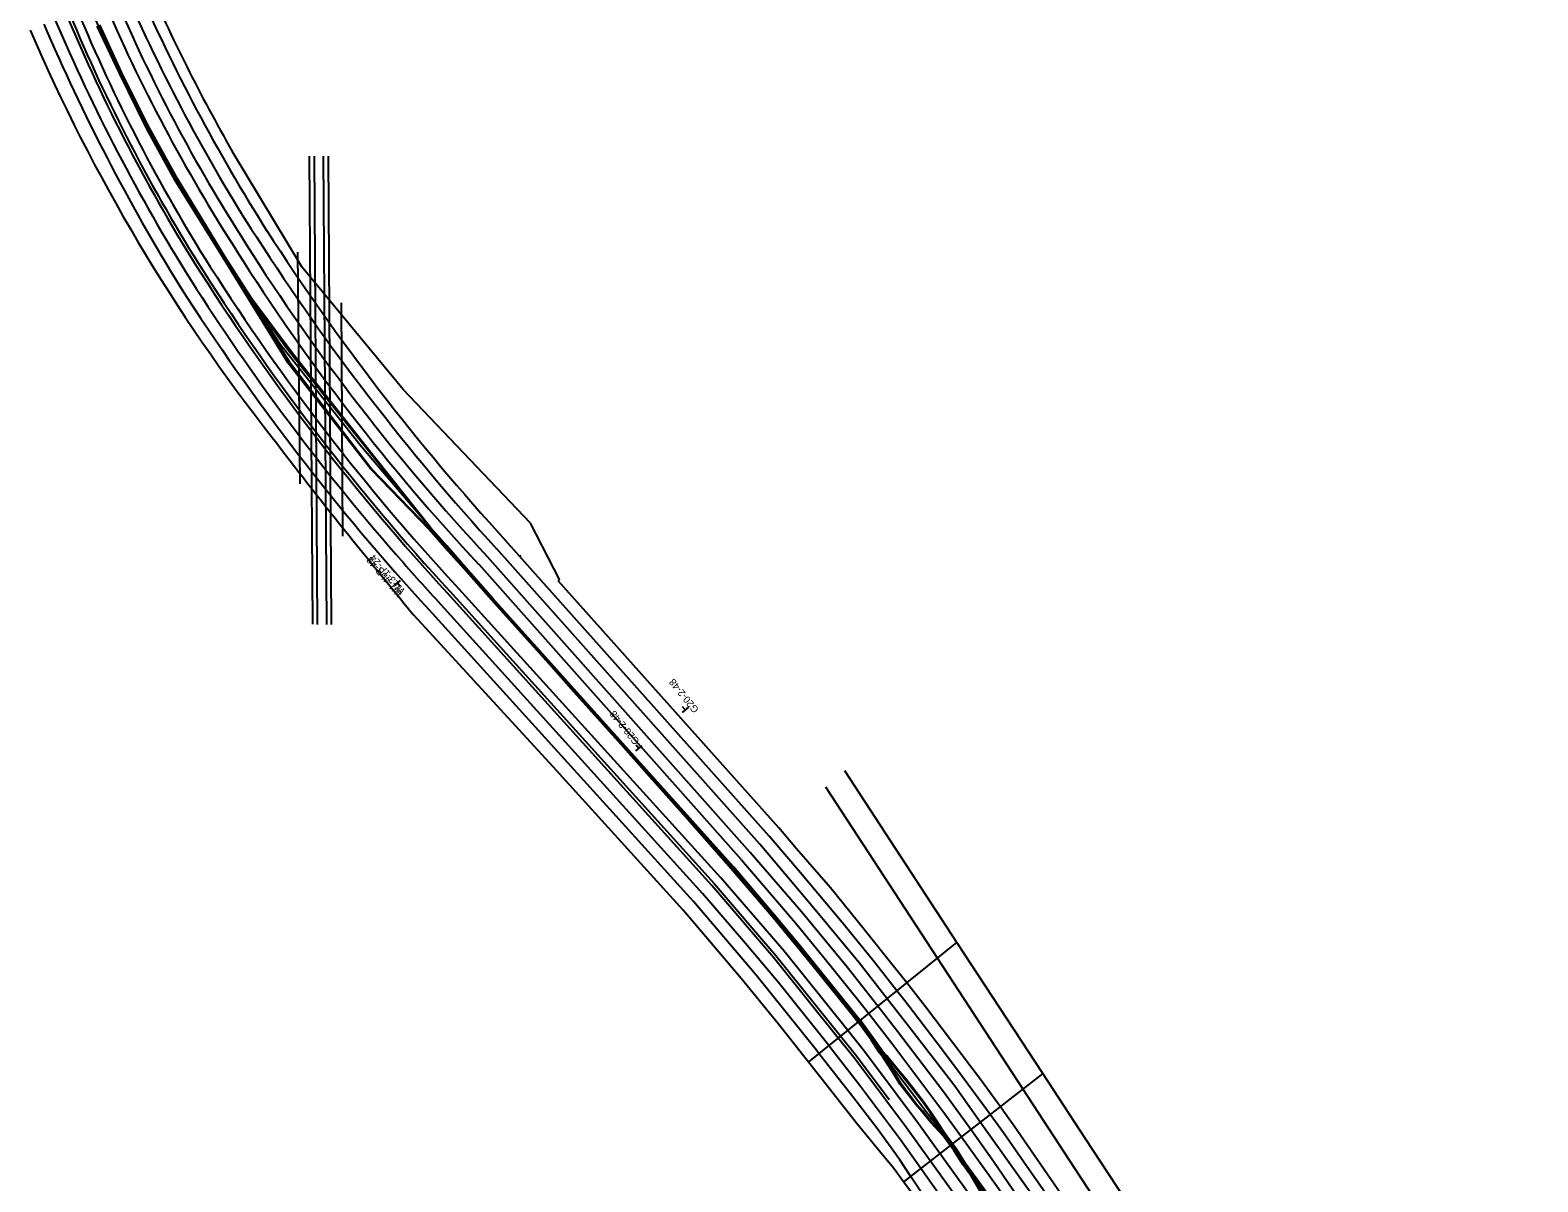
# Model space of a CAD drawing. Extents: x 1691089 to 1704871, y 694247 to 736350.
# Drawn here: x 1695879 to 1697359, y 720467 to 721597 of the extents above; entities that cross this region are included whole.
import ezdxf

# ---------------------------------------------------------------- set-up
doc = ezdxf.new("R2010")
doc.units = 0
for name, color, linetype in [('BR_X_Rail_Text', 7, 'Continuous'), ('BR_X_Slab_Object', 7, 'Continuous'), ('MT_P_Drums', 7, 'Continuous'), ('MT_P_Edge_Line', 7, 'Continuous'), ('PM_P_Channelizing_Line', 7, 'Continuous'), ('PM_X_Channelizing_Line', 7, 'Continuous'), ('PM_X_Dotted_Line', 7, 'Continuous'), ('PM_X_Edge_Line', 7, 'Continuous'), ('PM_X_Lane_Line', 7, 'Continuous'), ('PV_X_EOP', 7, 'Continuous'), ('PV_X_Shoulder', 7, 'Continuous'), ('RD_X_Concrete_Barrier', 7, 'Continuous'), ('SC_Scratch1', 7, 'Continuous'), ('SC_Scratch2', 7, 'Continuous'), ('SN_P_Signs', 7, 'Continuous')]:
    doc.layers.add(name, color=color, linetype=linetype)

msp = doc.modelspace()

# ---------------------------------------------------------------- linework, layer by layer
at = {"layer": 'BR_X_Rail_Text'}
for p, q in [((1696152.9, 721473.9), (1696156.4, 721014.4)), ((1696161.2, 721014.3), (1696158.3, 721473.8)), ((1696166.7, 721473.7), (1696170.1, 721014.2)), ((1696174.9, 721014.2), (1696172.1, 721473.7))]:
    msp.add_line(p, q, dxfattribs=at)
at = {"layer": 'BR_X_Slab_Object'}
for p, q in [((1696141.6, 721379.4), (1696143.8, 721152.3)), ((1696186.2, 721100.8), (1696184.7, 721329.9))]:
    msp.add_line(p, q, dxfattribs=at)
at = {"layer": 'MT_P_Drums'}
msp.add_line((1696901.4, 720309.1), (1696803.1, 720472.6), dxfattribs=at)
msp.add_lwpolyline([(1696291, 721046.9), (1696291, 721046.9), (1696550.5, 720759.9), (1696611.3, 720689.2), (1696690.3, 720590.8), (1696722.5, 720547.9)], dxfattribs=at)
for centre, radius, start, end in [((1697453.6, 722251.7), 1663.1, 202.5428, 212.3875), ((1697945.5, 722571.4), 2249.7, 212.5534, 222.6591)]:
    msp.add_arc(centre, radius, start, end, dxfattribs=at)
at = {"layer": 'MT_P_Edge_Line'}
msp.add_line((1696548.3, 720758), (1696288.8, 721044.9), dxfattribs=at)
for points in [[(1696672.4, 720608.3), (1696609, 720687.3), (1696548.3, 720758)], [(1696720.1, 720546.1), (1696688, 720588.9), (1696672.4, 720608.3)], [(1696762.8, 720487.7), (1696739.4, 720520.3), (1696720.1, 720546.1)], [(1696888.9, 720301.7), (1696809, 720423.3), (1696762.8, 720487.7)]]:
    msp.add_lwpolyline(points, dxfattribs=at)
for centre, radius, start, end in [((1697453.6, 722251.7), 1666.1, 202.5428, 212.3877), ((1697945.5, 722571.4), 2252.7, 212.5533, 222.6591)]:
    msp.add_arc(centre, radius, start, end, dxfattribs=at)
at = {"layer": 'PM_P_Channelizing_Line'}
msp.add_lwpolyline([(1696910.2, 720315.4), (1696907.1, 720320.2), (1696867.4, 720381.7), (1696850.4, 720407.5), (1696800, 720481.6), (1696695.8, 720618.7), (1696638.3, 720693.3), (1696578.4, 720765.8), (1696308.4, 721066.1), (1696204.3, 721188.4), (1696124.9, 721288.6), (1696069.9, 721373.8), (1696004.2, 721483.9), (1695952.8, 721586.7), (1695915.1, 721673.2)], dxfattribs=at)
at = {"layer": 'PM_X_Channelizing_Line'}
for points in [[(1696663.2, 720600.9), (1696613.4, 720663.3), (1696581.4, 720701.2)], [(1696711, 720538.6), (1696693.4, 720562.1), (1696665.9, 720597.4), (1696663.2, 720600.9)], [(1696753.4, 720480.4), (1696733.4, 720508.6), (1696711, 720538.6)], [(1696878.6, 720295.6), (1696837, 720360.8), (1696810.7, 720399.6), (1696753.4, 720480.4)]]:
    msp.add_lwpolyline(points, dxfattribs=at)
at = {"layer": 'PM_X_Dotted_Line'}
for p, q in [((1696539.3, 720750.2), (1696279.8, 721036.7)), ((1696581.4, 720701.2), (1696539.3, 720750.2))]:
    msp.add_line(p, q, dxfattribs=at)
msp.add_arc((1697937, 722563.4), 2253.3, 221.0668, 222.6525, dxfattribs=at)
at = {"layer": 'PM_X_Edge_Line'}
for p, q in [((1696577.5, 720783.1), (1696319.8, 721073)), ((1696557.2, 720765.7), (1696297, 721052.3))]:
    msp.add_line(p, q, dxfattribs=at)
for points in [[(1696577.5, 720783.1), (1696630.4, 720721.5), (1696660, 720685.3), (1696692.5, 720645), (1696702.4, 720632.4)], [(1696681.7, 720615.8), (1696619.3, 720693.5), (1696557.2, 720765.7)], [(1696702.4, 720632.4), (1696724.9, 720603.4), (1696777.1, 720533.9), (1696793.3, 720511.4)], [(1696729.3, 720553.7), (1696698.3, 720595.1), (1696681.7, 720615.8)], [(1696772.3, 720495), (1696749.7, 720526.5), (1696729.3, 720553.7)], [(1696793.3, 720511.4), (1696827.7, 720463.5), (1696874.8, 720395.2), (1696906.7, 720346.8), (1696927.6, 720314.4), (1697062.4, 720097), (1697098.5, 720038.5), (1697133.9, 719981.7), (1697162.2, 719935.7), (1697199.3, 719874.8)], [(1696899.2, 720307.9), (1696819.3, 720429.5), (1696772.3, 720495)]]:
    msp.add_lwpolyline(points, dxfattribs=at)
for centre, radius, start, end in [((1697480.8, 722263.3), 1684.3, 202.5458, 212.2218), ((1697506.5, 722297), 1693.7, 203.2478, 212.7106), ((1697834.5, 722488.4), 2073.2, 212.2654, 223.0597), ((1697936.6, 722564.4), 2230.4, 212.5219, 222.6822)]:
    msp.add_arc(centre, radius, start, end, dxfattribs=at)
at = {"layer": 'PM_X_Lane_Line'}
for p, q in [((1696595.3, 720798.5), (1696336.9, 721088.6)), ((1696586, 720790.5), (1696328.1, 721080.6))]:
    msp.add_line(p, q, dxfattribs=at)
for points in [[(1696711.2, 720639.5), (1696681.3, 720677.8), (1696636.4, 720732.1), (1696586, 720790.5)], [(1696720.4, 720646.9), (1696692.9, 720682), (1696648.3, 720736.2), (1696595.3, 720798.5)], [(1696811.9, 720525.8), (1696786.8, 720561.2), (1696743.7, 720617), (1696720.4, 720646.9)], [(1696802.5, 720518.5), (1696775.9, 720555.5), (1696730.6, 720614.8), (1696711.2, 720639.5)], [(1697081.4, 720110), (1696950.9, 720320.3), (1696884.6, 720422.4), (1696859.8, 720458.5), (1696811.9, 720525.8)], [(1697209.4, 719880.9), (1697169.4, 719945.8), (1696946, 720306.1), (1696902, 720374), (1696825, 720487.3), (1696802.5, 720518.5)]]:
    msp.add_lwpolyline(points, dxfattribs=at)
for centre, radius, start, end in [((1697484.5, 722282.9), 1656.3, 203.1, 212.7129), ((1697502.3, 722296.6), 1666.4, 203.2892, 212.7764), ((1697578.7, 722319.3), 1820, 203.0043, 212.0768), ((1697886.9, 722529.7), 2128.4, 212.4479, 222.9118), ((1698021.9, 722630.4), 2283.9, 212.7617, 222.4608), ((1697937, 722563.4), 2253.3, 212.4985, 221.0668)]:
    msp.add_arc(centre, radius, start, end, dxfattribs=at)
at = {"layer": 'PV_X_EOP'}
for p, q in [((1696604.5, 720806.4), (1696345.9, 721096.7)), ((1696360.8, 721080.4), (1696359.7, 721081.8)), ((1696530.2, 720742.4), (1696270.7, 721028.5)), ((1696873.2, 720573.4), (1696789, 720702.1)), ((1696853.8, 720558.4), (1696769.9, 720686.7))]:
    msp.add_line(p, q, dxfattribs=at)
for points in [[(1696730, 720654.7), (1696706.3, 720684.9), (1696676.3, 720721.7), (1696635.4, 720770.3), (1696604.5, 720806.4)], [(1696653.5, 720593.1), (1696650.8, 720596.6), (1696591.7, 720670), (1696530.2, 720742.4)], [(1696821.5, 720533.3), (1696815.3, 720541.9), (1696794.1, 720570.7), (1696773.9, 720597.7), (1696737.8, 720644.8), (1696730, 720654.7)], [(1696743.5, 720472.7), (1696732.9, 720488.7), (1696710.5, 720519.4), (1696686.8, 720550.6), (1696653.5, 720593.1)], [(1697045.1, 720311.8), (1696915, 720509.5), (1696873.2, 720573.4)], [(1697103.1, 720178.1), (1696904.8, 720480.3), (1696853.8, 720558.4)], [(1697359.2, 719730.4), (1697341, 719753.2), (1697308.3, 719796), (1697294.5, 719815.3), (1697286.5, 719827.3), (1697275.5, 719843.1), (1697259.5, 719867.2), (1697226.8, 719917.4), (1697204.3, 719951.5), (1697169.5, 720005), (1697022.9, 720228.1), (1697002, 720261.3), (1696982.9, 720292.3), (1696952.2, 720341.3), (1696912.9, 720401.2), (1696877.4, 720453.8), (1696857.6, 720482.4), (1696834.7, 720515.2), (1696821.5, 720533.3)], [(1696854.4, 720283), (1696812.4, 720360.8), (1696793.9, 720393.5), (1696768.8, 720434.4), (1696743.5, 720472.7)]]:
    msp.add_lwpolyline(points, dxfattribs=at)
for centre, radius, start, end in [((1697608.4, 722349.5), 1772.3, 203.5031, 212.3583), ((1697687.4, 722372.2), 1952.6, 203.1914, 211.7045), ((1698029.3, 722636.9), 2281.7, 212.7967, 222.4558), ((1698004, 722616.3), 2350.6, 212.7108, 222.4927)]:
    msp.add_arc(centre, radius, start, end, dxfattribs=at)
at = {"layer": 'PV_X_Shoulder'}
for p, q in [((1696077.4, 721478.4), (1696145.5, 721365.4)), ((1696094, 721332.7), (1696068.9, 721373.6)), ((1696096.8, 721333.8), (1696070.6, 721374.7)), ((1696245.2, 721244.8), (1696145.5, 721365.4)), ((1696132.5, 721270.7), (1696094, 721332.7)), ((1696137.3, 721279.6), (1696096.8, 721333.8)), ((1696218.4, 721176.7), (1696137.3, 721279.6)), ((1696213.6, 721166.6), (1696132.5, 721270.7)), ((1696370.2, 721113.6), (1696245.2, 721244.8)), ((1696272.1, 721109.2), (1696218.4, 721176.7)), ((1696213.6, 721166.6), (1696270.8, 721107.4)), ((1696398.8, 721058.3), (1696370.2, 721113.6)), ((1696398.8, 721058.3), (1696397.4, 721057.1)), ((1696614, 720814.5), (1696397.4, 721057.1)), ((1696392.7, 720874.4), (1696259.9, 721018.6)), ((1696520.3, 720733.8), (1696392.7, 720874.4))]:
    msp.add_line(p, q, dxfattribs=at)
for points in [[(1696070.6, 721374.7), (1696023.9, 721451.4), (1695995.6, 721502.6), (1695968.9, 721556.3), (1695947.4, 721602.5)], [(1696068.9, 721373.6), (1696021.6, 721449.9), (1695993.5, 721501.4), (1695967, 721555.1), (1695944.9, 721601.4)], [(1696567.4, 720774.5), (1696519.8, 720828.3), (1696487.3, 720865), (1696459.2, 720896.5), (1696410.4, 720951.1), (1696390.9, 720973), (1696347, 721021.8), (1696332, 721038.5), (1696305.2, 721068.7), (1696286.3, 721089.8), (1696270.8, 721107.4)], [(1696569.5, 720776.3), (1696460.9, 720897.4), (1696382.1, 720985.4), (1696333.3, 721039.8), (1696306.8, 721069.9), (1696288.1, 721091.3), (1696272.1, 721109.2)], [(1696739.7, 720662.4), (1696726.5, 720679.3), (1696698, 720714.7), (1696664.7, 720755.6), (1696631.5, 720794.1), (1696614, 720814.5)], [(1696691.9, 720624), (1696691.8, 720624.1), (1696648.3, 720678.2), (1696632, 720698), (1696607.2, 720727.8), (1696567.4, 720774.5)], [(1696694, 720625.7), (1696650.6, 720679.6), (1696634.4, 720699.5), (1696609.6, 720729.3), (1696569.5, 720776.3)], [(1696643.1, 720584.7), (1696613.7, 720621.9), (1696577.2, 720666.9), (1696546.1, 720703.3), (1696520.3, 720733.8)], [(1696831.4, 720541), (1696813.2, 720566.3), (1696784.6, 720603.9), (1696758.1, 720639), (1696739.7, 720662.4)], [(1696784.5, 720504.6), (1696778, 720513.4), (1696769.1, 720526.7), (1696763.4, 720535.6), (1696756.2, 720545.8), (1696745.5, 720559.6), (1696738.3, 720568.7), (1696729.7, 720579.2), (1696720.1, 720591), (1696715.9, 720595.6), (1696707.1, 720608), (1696694.2, 720625.5), (1696694, 720625.7)], [(1696782.4, 720502.9), (1696775.7, 720512), (1696763, 720525.7), (1696754.6, 720536.3), (1696748.2, 720543.3), (1696733.3, 720562.9), (1696725.2, 720576), (1696716.4, 720589.3), (1696712.9, 720593.7), (1696704.8, 720606.6), (1696691.9, 720624)], [(1696736.5, 720467.2), (1696726.9, 720480.2), (1696709.6, 720501.1), (1696690.2, 720524.7), (1696655.3, 720569.2), (1696643.1, 720584.7)], [(1697122.4, 720095.2), (1697102.7, 720126.1), (1697068.5, 720178), (1696936.2, 720389.9), (1696845.1, 720521.9), (1696831.4, 720541)], [(1696846.5, 720410.1), (1696843.5, 720415.1), (1696837.2, 720424.7), (1696825.5, 720441.8), (1696794.7, 720484.1), (1696786.2, 720497.7), (1696782.4, 720502.9)], [(1696848.8, 720411.6), (1696845.9, 720416.5), (1696839.5, 720426.2), (1696827.9, 720443.2), (1696797.1, 720485.5), (1696788.5, 720499.2), (1696784.5, 720504.6)], [(1696883.7, 720208.5), (1696795.3, 720373.7), (1696758.7, 720434.7), (1696745.9, 720454.4), (1696736.5, 720467.2)]]:
    msp.add_lwpolyline(points, dxfattribs=at)
for centre, radius, start, end in [((1697661.8, 722380.1), 1822.9, 203.7143, 209.6441), ((1697524.9, 722305.5), 1791.6, 203.2793, 218.1941), ((1700238.3, 724343.9), 5185.1, 217.3575, 219.8901)]:
    msp.add_arc(centre, radius, start, end, dxfattribs=at)
at = {"layer": 'RD_X_Concrete_Barrier'}
for points in [[(1695946.9, 721602.3), (1695968.4, 721556), (1695995.1, 721502.4), (1696023.4, 721451.1), (1696070.1, 721374.4)], [(1695945.5, 721601.6), (1695967.5, 721555.4), (1695994.1, 721501.6), (1696022.1, 721450.2), (1696069.4, 721373.9)], [(1696069.4, 721373.9), (1696089.2, 721341.9), (1696133.3, 721272.3), (1696214.5, 721166.7)], [(1696221.1, 721172.2), (1696130.8, 721285.4), (1696089.8, 721342.2), (1696070.1, 721374.4)], [(1696568.1, 720775), (1696520.3, 720828.6), (1696487.7, 720865.5), (1696459.7, 720896.8), (1696410.6, 720951.3), (1696391.4, 720973), (1696381.4, 720984.3), (1696347.1, 721022.2), (1696332.4, 721038.8), (1696305.8, 721069), (1696286.9, 721090.1), (1696271.2, 721108.1), (1696214.5, 721166.7)], [(1696568.8, 720775.7), (1696521, 720829.4), (1696460, 720897.3), (1696411.3, 720951.6), (1696392, 720973.6), (1696381.9, 720985.1), (1696332.9, 721039.6), (1696306.5, 721069.6), (1696287.7, 721090.9), (1696272.2, 721108.7), (1696221.1, 721172.2)], [(1696692.6, 720624.5), (1696649, 720678.6), (1696632.8, 720698.5), (1696608, 720728.3), (1696568.1, 720775)], [(1696693.3, 720625.1), (1696649.9, 720679.2), (1696633.6, 720699), (1696608.8, 720728.8), (1696568.8, 720775.7)], [(1696783, 720503.4), (1696776.4, 720512.4), (1696763.7, 720526.2), (1696755.4, 720536.7), (1696748.9, 720543.7), (1696734.1, 720563.3), (1696725.9, 720576.5), (1696717.2, 720589.7), (1696713.6, 720594.1), (1696705.5, 720607), (1696692.6, 720624.5)], [(1696783.8, 720504), (1696777.3, 720513), (1696768.3, 720526.2), (1696762.6, 720535.2), (1696755.4, 720545.3), (1696744.7, 720559.1), (1696737.6, 720568.2), (1696728.9, 720578.7), (1696719.3, 720590.5), (1696715.2, 720595.1), (1696706.4, 720607.5), (1696693.4, 720625), (1696693.3, 720625.1)], [(1696847.2, 720410.6), (1696844.3, 720415.5), (1696837.9, 720425.2), (1696826.3, 720442.2), (1696795.5, 720484.5), (1696786.9, 720498.2), (1696783, 720503.4)], [(1696848.1, 720411.1), (1696845.1, 720416), (1696838.8, 720425.7), (1696827.1, 720442.8), (1696796.3, 720485.1), (1696787.7, 720498.7), (1696783.8, 720504)]]:
    msp.add_lwpolyline(points, dxfattribs=at)
at = {"layer": 'SC_Scratch1'}
for p, q in [((1696789, 720702.1), (1696679, 720870.5)), ((1696769.9, 720686.7), (1696660.4, 720854.5)), ((1696643.1, 720584.7), (1696789, 720702.1)), ((1696738, 720661.1), (1696739.9, 720662.6)), ((1696873.2, 720573.4), (1696736.5, 720467.2))]:
    msp.add_line(p, q, dxfattribs=at)
at = {"layer": 'SC_Scratch2'}
for points in [[(1696691.8, 720623.9), (1696638.3, 720693.3), (1696578.4, 720765.8), (1696308.4, 721066.1), (1696204.3, 721188.4), (1696124.9, 721288.6), (1696069.9, 721373.8), (1696004.2, 721483.9), (1695952.8, 721586.7), (1695915.1, 721673.2)], [(1696936.4, 720274.7), (1696910.5, 720315), (1696907.1, 720320.2), (1696867.4, 720381.7), (1696850.4, 720407.5), (1696800, 720481.6), (1696695.8, 720618.7), (1696638.3, 720693.3), (1696578.4, 720765.8), (1696308.4, 721066.1), (1696204.3, 721188.4), (1696124.9, 721288.6), (1696069.9, 721373.8), (1696004.2, 721483.9), (1695952.8, 721586.7), (1695915.1, 721673.2)]]:
    msp.add_lwpolyline(points, dxfattribs=at)
at = {"layer": 'SN_P_Signs'}
for p, q in [((1696236.7, 721052.3), (1696242.8, 721057.4)), ((1696239.8, 721054.9), (1696242.4, 721051.8)), ((1696525.3, 720932.9), (1696519.2, 720927.8)), ((1696522.3, 720930.3), (1696519.7, 720933.4)), ((1696479.7, 720895.2), (1696473.5, 720890.1)), ((1696476.6, 720892.6), (1696474.1, 720895.7))]:
    msp.add_line(p, q, dxfattribs=at)

# ---------------------------------------------------------------- texts
at = {"layer": 'SC_Scratch1'}
for s, rotation, p in [('W1-4bR-48', 130.4128, (1696244.9, 721045)), ('W13-1P-24', 130.4128, (1696247.8, 721047.5)), ('G20-2-48', 128.9741, (1696536, 720930.9)), ('G20-2-48', 128.9741, (1696477.8, 720899.7))]:
    msp.add_text(s, height=7, rotation=rotation, dxfattribs=at).set_placement(p)

doc.saveas('drawing.dxf')
